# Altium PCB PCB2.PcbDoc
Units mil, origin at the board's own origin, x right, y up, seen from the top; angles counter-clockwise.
Board outline 6000 x 4000 mil, 2 copper layers (Top Layer, Bottom Layer); 84 components, 0 nets, 252 pads, 0 vias.
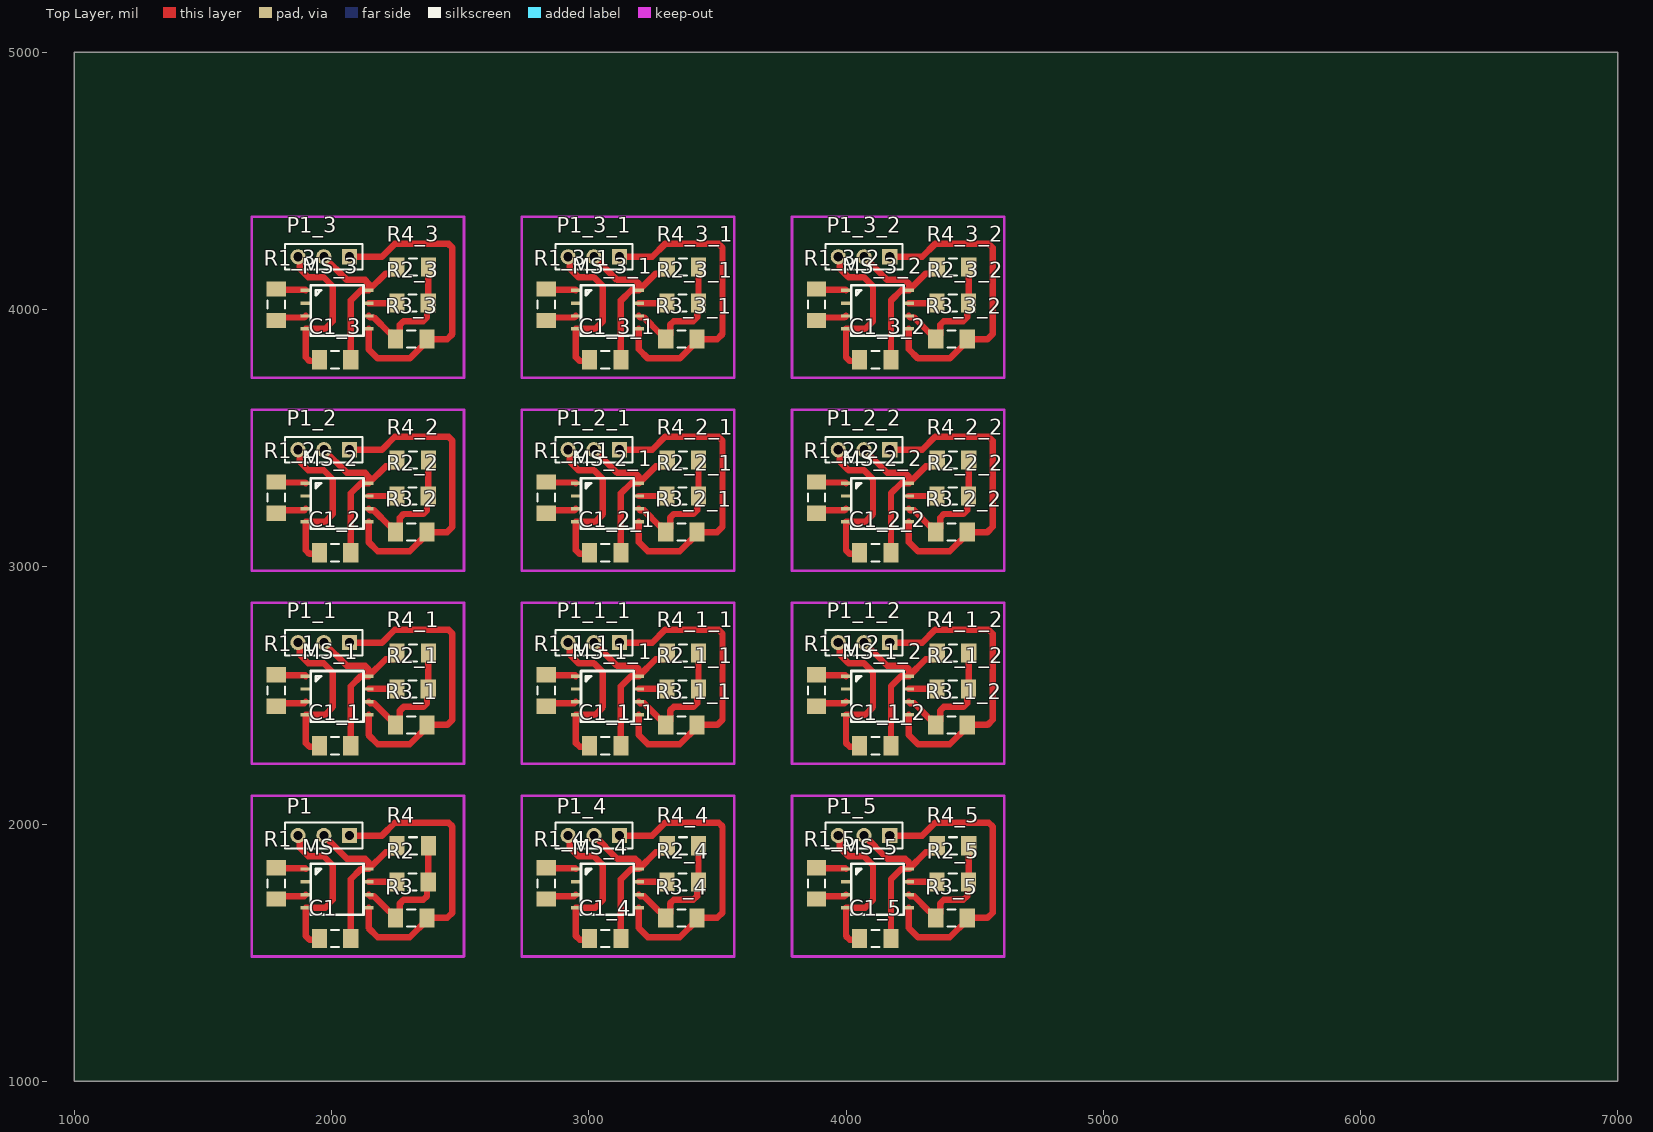
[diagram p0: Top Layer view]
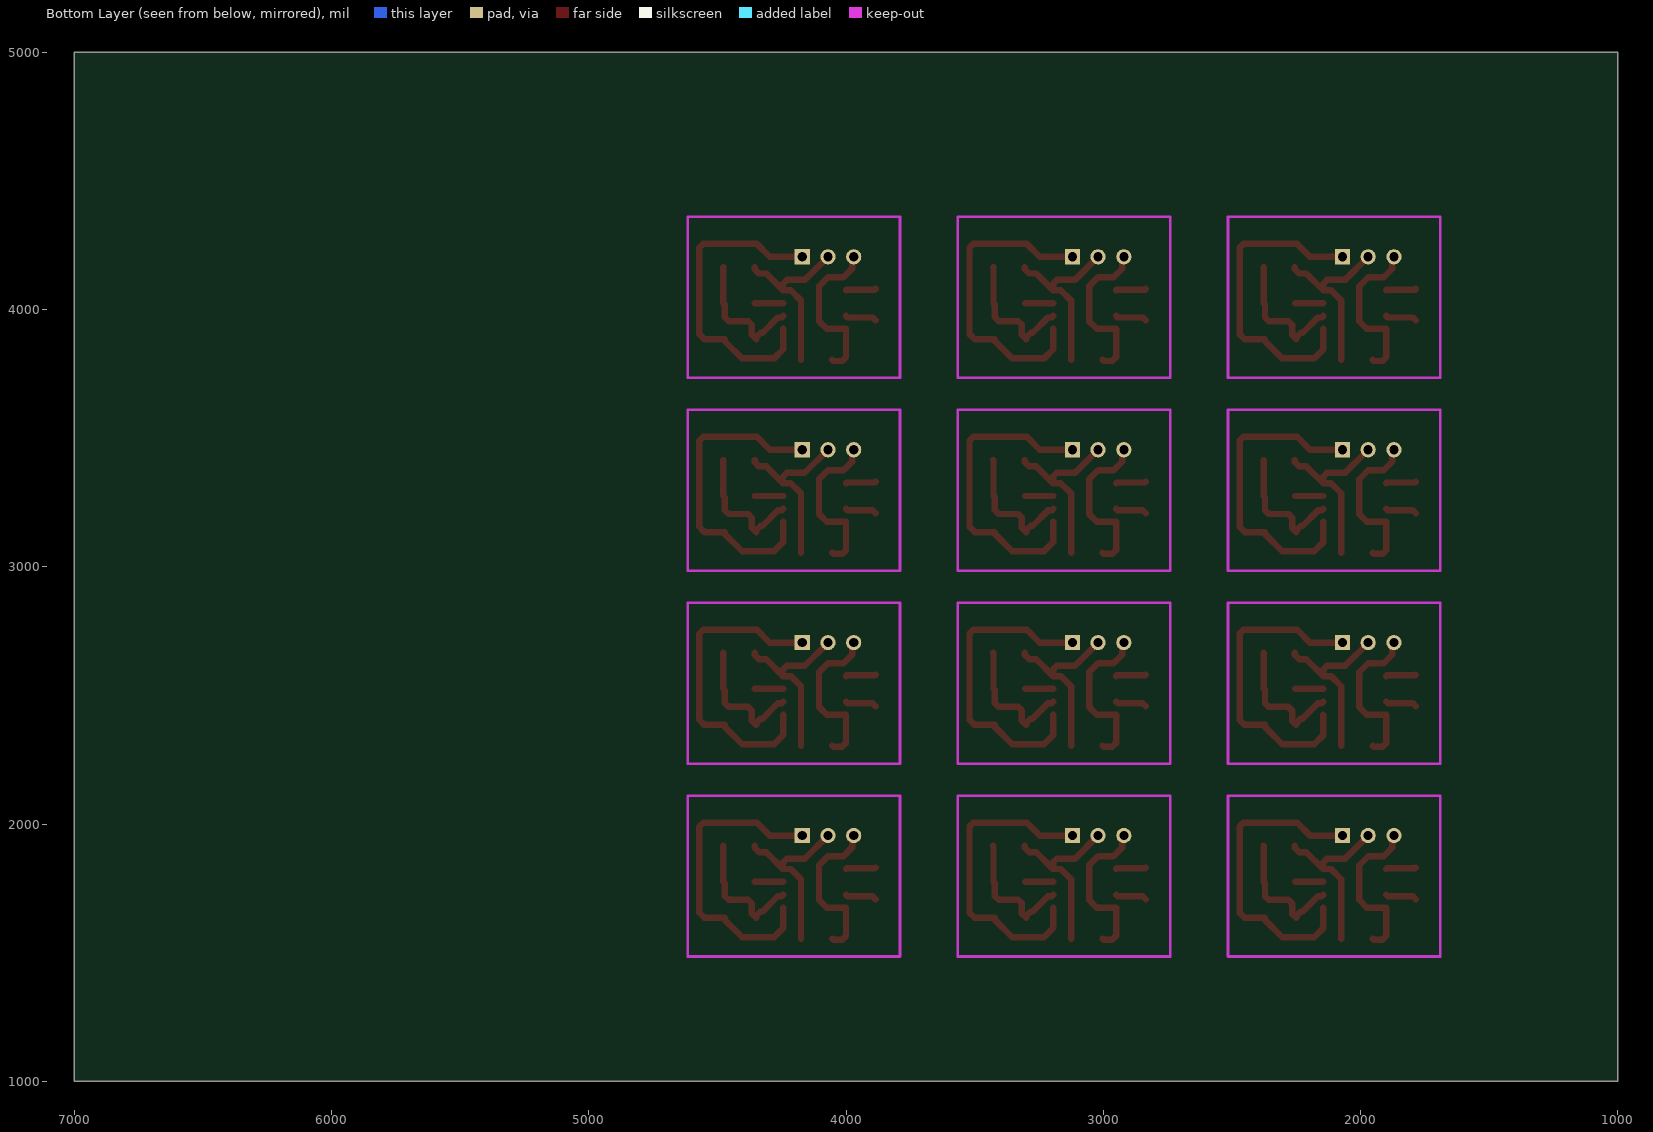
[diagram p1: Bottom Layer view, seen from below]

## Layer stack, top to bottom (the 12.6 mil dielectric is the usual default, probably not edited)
Top Solder: solder mask 0.4, Solder Resist, Dk 3.5
Top Layer: signal copper 1.4
Dielectric 1: dielectric 12.6, FR-4, Dk 4.8
Bottom Layer: signal copper 1.4
Bottom Solder: solder mask 0.4, Solder Resist, Dk 3.5

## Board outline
1000,1000 7000,1000 7000,5000 1000,5000

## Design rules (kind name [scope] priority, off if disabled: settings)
Clearance [All] p1: gap=10 ignorepadtopadclearanceinfootprint=FALSE except(0: Arc-Hole Track-Hole SMDPad-Hole THPad-Hole Via-Hole Fill-Hole Poly-Hole Region-Hole Text-Hole)
PolygonConnect [All] p1: connectstyle=Relief reliefconductorwidth=10 reliefentries=4 polygonreliefangle="90 Angle" airgapwidth=10
RoutingVias [All] p1: holewidth=28 width=50 viastyle="Through Hole" minholewidth=28 minwidth=50 maxholewidth=28 maxwidth=50
SolderMaskExpansion [All] p1: expansion=4
Width [All] p1: maxlimit=10 minlimit=10 preferedwidth=10
30 further rules are at their usual default settings.

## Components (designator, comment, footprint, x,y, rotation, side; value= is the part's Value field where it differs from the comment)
C1 "Cap" CAPC3216M 2013.98,1554.53 r0 top value=0.1muF
C1_1 "Cap" CAPC3216M 2013.98,2304.53 r0 top value=0.1muF (schematic designator C1)
C1_1_1 "Cap" CAPC3216M 3063.98,2304.53 r0 top value=0.1muF (schematic designator C1)
C1_1_2 "Cap" CAPC3216M 4113.98,2304.53 r0 top value=0.1muF (schematic designator C1)
C1_2 "Cap" CAPC3216M 2013.98,3054.53 r0 top value=0.1muF (schematic designator C1)
C1_2_1 "Cap" CAPC3216M 3063.98,3054.53 r0 top value=0.1muF (schematic designator C1)
C1_2_2 "Cap" CAPC3216M 4113.98,3054.53 r0 top value=0.1muF (schematic designator C1)
C1_3 "Cap" CAPC3216M 2013.98,3804.53 r0 top value=0.1muF (schematic designator C1)
C1_3_1 "Cap" CAPC3216M 3063.98,3804.53 r0 top value=0.1muF (schematic designator C1)
C1_3_2 "Cap" CAPC3216M 4113.98,3804.53 r0 top value=0.1muF (schematic designator C1)
C1_4 "Cap" CAPC3216M 3063.98,1554.53 r0 top value=0.1muF (schematic designator C1)
C1_5 "Cap" CAPC3216M 4113.98,1554.53 r0 top value=0.1muF (schematic designator C1)
MS "MagnetSensor" AD22151 1900,1825 r0 top
MS_1 "MagnetSensor" AD22151 1900,2575 r0 top (schematic designator MS)
MS_1_1 "MagnetSensor" AD22151 2950,2575 r0 top (schematic designator MS)
MS_1_2 "MagnetSensor" AD22151 4000,2575 r0 top (schematic designator MS)
MS_2 "MagnetSensor" AD22151 1900,3325 r0 top (schematic designator MS)
MS_2_1 "MagnetSensor" AD22151 2950,3325 r0 top (schematic designator MS)
MS_2_2 "MagnetSensor" AD22151 4000,3325 r0 top (schematic designator MS)
MS_3 "MagnetSensor" AD22151 1900,4075 r0 top (schematic designator MS)
MS_3_1 "MagnetSensor" AD22151 2950,4075 r0 top (schematic designator MS)
MS_3_2 "MagnetSensor" AD22151 4000,4075 r0 top (schematic designator MS)
MS_4 "MagnetSensor" AD22151 2950,1825 r0 top (schematic designator MS)
MS_5 "MagnetSensor" AD22151 4000,1825 r0 top (schematic designator MS)
P1 "Header 3" HDR1X3 2070,1955 r180 top (schematic designator P?)
P1_1 "Header 3" HDR1X3 2070,2705 r180 top (schematic designator P?)
P1_1_1 "Header 3" HDR1X3 3120,2705 r180 top (schematic designator P?)
P1_1_2 "Header 3" HDR1X3 4170,2705 r180 top (schematic designator P?)
P1_2 "Header 3" HDR1X3 2070,3455 r180 top (schematic designator P?)
P1_2_1 "Header 3" HDR1X3 3120,3455 r180 top (schematic designator P?)
P1_2_2 "Header 3" HDR1X3 4170,3455 r180 top (schematic designator P?)
P1_3 "Header 3" HDR1X3 2070,4205 r180 top (schematic designator P?)
P1_3_1 "Header 3" HDR1X3 3120,4205 r180 top (schematic designator P?)
P1_3_2 "Header 3" HDR1X3 4170,4205 r180 top (schematic designator P?)
P1_4 "Header 3" HDR1X3 3120,1955 r180 top (schematic designator P?)
P1_5 "Header 3" HDR1X3 4170,1955 r180 top (schematic designator P?)
R1 "Res3" RESC3216M 1785,1768.98 r90 top value=4.7K
R1_1 "Res3" RESC3216M 1785,2518.98 r90 top value=4.7K (schematic designator R1)
R1_1_1 "Res3" RESC3216M 2835,2518.98 r90 top value=4.7K (schematic designator R1)
R1_1_2 "Res3" RESC3216M 3885,2518.98 r90 top value=4.7K (schematic designator R1)
R1_2 "Res3" RESC3216M 1785,3268.98 r90 top value=4.7K (schematic designator R1)
R1_2_1 "Res3" RESC3216M 2835,3268.98 r90 top value=4.7K (schematic designator R1)
R1_2_2 "Res3" RESC3216M 3885,3268.98 r90 top value=4.7K (schematic designator R1)
R1_3 "Res3" RESC3216M 1785,4018.98 r90 top value=4.7K (schematic designator R1)
R1_3_1 "Res3" RESC3216M 2835,4018.98 r90 top value=4.7K (schematic designator R1)
R1_3_2 "Res3" RESC3216M 3885,4018.98 r90 top value=4.7K (schematic designator R1)
R1_4 "Res3" RESC3216M 2835,1768.98 r90 top value=4.7K (schematic designator R1)
R1_5 "Res3" RESC3216M 3885,1768.98 r90 top value=4.7K (schematic designator R1)
R2 "Res3" RESC3216M 2315,1775 r0 top value=4.7K
R2_1 "Res3" RESC3216M 2315,2525 r0 top value=4.7K (schematic designator R2)
R2_1_1 "Res3" RESC3216M 3365,2525 r0 top value=4.7K (schematic designator R2)
R2_1_2 "Res3" RESC3216M 4415,2525 r0 top value=4.7K (schematic designator R2)
R2_2 "Res3" RESC3216M 2315,3275 r0 top value=4.7K (schematic designator R2)
R2_2_1 "Res3" RESC3216M 3365,3275 r0 top value=4.7K (schematic designator R2)
R2_2_2 "Res3" RESC3216M 4415,3275 r0 top value=4.7K (schematic designator R2)
R2_3 "Res3" RESC3216M 2315,4025 r0 top value=4.7K (schematic designator R2)
R2_3_1 "Res3" RESC3216M 3365,4025 r0 top value=4.7K (schematic designator R2)
R2_3_2 "Res3" RESC3216M 4415,4025 r0 top value=4.7K (schematic designator R2)
R2_4 "Res3" RESC3216M 3365,1775 r0 top value=4.7K (schematic designator R2)
R2_5 "Res3" RESC3216M 4415,1775 r0 top value=4.7K (schematic designator R2)
R3 "Res3" RESC3216M 2310,1635 r0 top value=4.7K
R3_1 "Res3" RESC3216M 2310,2385 r0 top value=4.7K (schematic designator R3)
R3_1_1 "Res3" RESC3216M 3360,2385 r0 top value=4.7K (schematic designator R3)
R3_1_2 "Res3" RESC3216M 4410,2385 r0 top value=4.7K (schematic designator R3)
R3_2 "Res3" RESC3216M 2310,3135 r0 top value=4.7K (schematic designator R3)
R3_2_1 "Res3" RESC3216M 3360,3135 r0 top value=4.7K (schematic designator R3)
R3_2_2 "Res3" RESC3216M 4410,3135 r0 top value=4.7K (schematic designator R3)
R3_3 "Res3" RESC3216M 2310,3885 r0 top value=4.7K (schematic designator R3)
R3_3_1 "Res3" RESC3216M 3360,3885 r0 top value=4.7K (schematic designator R3)
R3_3_2 "Res3" RESC3216M 4410,3885 r0 top value=4.7K (schematic designator R3)
R3_4 "Res3" RESC3216M 3360,1635 r0 top value=4.7K (schematic designator R3)
R3_5 "Res3" RESC3216M 4410,1635 r0 top value=4.7K (schematic designator R3)
R4 "Res3" RESC3216M 2316.02,1915 r0 top value=4.7K
R4_1 "Res3" RESC3216M 2316.02,2665 r0 top value=4.7K (schematic designator R4)
R4_1_1 "Res3" RESC3216M 3366.02,2665 r0 top value=4.7K (schematic designator R4)
R4_1_2 "Res3" RESC3216M 4416.02,2665 r0 top value=4.7K (schematic designator R4)
R4_2 "Res3" RESC3216M 2316.02,3415 r0 top value=4.7K (schematic designator R4)
R4_2_1 "Res3" RESC3216M 3366.02,3415 r0 top value=4.7K (schematic designator R4)
R4_2_2 "Res3" RESC3216M 4416.02,3415 r0 top value=4.7K (schematic designator R4)
R4_3 "Res3" RESC3216M 2316.02,4165 r0 top value=4.7K (schematic designator R4)
R4_3_1 "Res3" RESC3216M 3366.02,4165 r0 top value=4.7K (schematic designator R4)
R4_3_2 "Res3" RESC3216M 4416.02,4165 r0 top value=4.7K (schematic designator R4)
R4_4 "Res3" RESC3216M 3366.02,1915 r0 top value=4.7K (schematic designator R4)
R4_5 "Res3" RESC3216M 4416.02,1915 r0 top value=4.7K (schematic designator R4)

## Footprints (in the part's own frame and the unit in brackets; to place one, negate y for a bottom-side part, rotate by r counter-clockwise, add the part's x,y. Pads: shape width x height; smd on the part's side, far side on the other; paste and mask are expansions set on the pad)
AD22151 [mm] "Magnetic Sensor"
  rect 1x0.33 smd: 1(0,0) 2(0,-1.27) 3(0,-2.54) 4(0,-3.81) 5(6.2,-3.81) 6(6.2,-2.54) 7(6.2,-1.27) 8(6.2,0)
  silkscreen extent 0.5,-4.5 5.7,0.5
CAPC3216M [mm] "Chip Capacitor, Body 3.2x1.6mm, IPC Low Density"
  rect 1.5x1.9 smd: 1(-1.55,0) 2(1.55,0)
  silkscreen extent -0.4,-0.85 0.4,0.85, body extent -1.7,-0.9 1.7,0.9, height 1.35
HDR1X3 [mm] "Connector; Header; 3 Position"
  rect 1.5x1.5 hole 0.9: 1(0,0)
  round 1.5 hole 0.9: 2(2.54,0) 3(5.08,0)
  silkscreen extent -1.27,-1.27 6.35,1.27
RESC3216M [mm] "Chip Resistor, Body 3.2x1.6mm, IPC Low Density"
  rect 1.5x1.9 smd: 1(-1.55,0) 2(1.55,0)
  silkscreen extent -0.4,-0.85 0.4,0.85, body extent -1.68,-0.87 1.68,0.87, height 0.71

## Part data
C1 C1_1 C1_1_1 C1_1_2 C1_2 C1_2_1 C1_2_2 C1_3 C1_3_1 C1_3_2 C1_4 C1_5: "Capacitor"
MS MS_1 MS_1_1 MS_1_2 MS_2 MS_2_1 MS_2_2 MS_3 MS_3_1 MS_3_2 MS_4 MS_5: library part Component_1
P1 P1_1 P1_1_1 P1_1_2 P1_2 P1_2_1 P1_2_2 P1_3 P1_3_1 P1_3_2 P1_4 P1_5: "Header, 3-Pin"
R1 R1_1 R1_1_1 R1_1_2 R1_2 R1_2_1 R1_2_2 R1_3 R1_3_1 R1_3_2 R1_4 R1_5 R2 R2_1 R2_1_1 R2_1_2 R2_2 R2_2_1 R2_2_2 R2_3 R2_3_1 R2_3_2 R2_4 R2_5 R3 R3_1 R3_1_1 R3_1_2 R3_2 R3_2_1 R3_2_2 R3_3 R3_3_1 R3_3_2 R3_4 R3_5 R4 R4_1 R4_1_1 R4_1_2 R4_2 R4_2_1 R4_2_2 R4_3 R4_3_1 R4_3_2 R4_4 R4_5: "Resistor"

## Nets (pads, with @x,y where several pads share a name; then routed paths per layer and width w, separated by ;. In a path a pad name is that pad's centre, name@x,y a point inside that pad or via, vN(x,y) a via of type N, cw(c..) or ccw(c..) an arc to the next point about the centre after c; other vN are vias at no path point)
pads on no net: C1.1 C1.2 C1_1.1 C1_1.2 C1_1_1.1 C1_1_1.2 C1_1_2.1 C1_1_2.2 C1_2.1 C1_2.2 C1_2_1.1 C1_2_1.2 C1_2_2.1 C1_2_2.2 C1_3.1 C1_3.2 C1_3_1.1 C1_3_1.2 C1_3_2.1 C1_3_2.2 C1_4.1 C1_4.2 C1_5.1 C1_5.2 MS.1 MS.2 MS.3 MS.4 MS.5 MS.6 MS.7 MS.8 MS_1.1 MS_1.2 MS_1.3 MS_1.4 MS_1.5 MS_1.6 MS_1.7 MS_1.8 MS_1_1.1 MS_1_1.2 MS_1_1.3 MS_1_1.4 MS_1_1.5 MS_1_1.6 MS_1_1.7 MS_1_1.8 MS_1_2.1 MS_1_2.2 MS_1_2.3 MS_1_2.4 MS_1_2.5 MS_1_2.6 MS_1_2.7 MS_1_2.8 MS_2.1 MS_2.2 MS_2.3 MS_2.4 MS_2.5 MS_2.6 MS_2.7 MS_2.8 MS_2_1.1 MS_2_1.2 MS_2_1.3 MS_2_1.4 MS_2_1.5 MS_2_1.6 MS_2_1.7 MS_2_1.8 MS_2_2.1 MS_2_2.2 MS_2_2.3 MS_2_2.4 MS_2_2.5 MS_2_2.6 MS_2_2.7 MS_2_2.8 MS_3.1 MS_3.2 MS_3.3 MS_3.4 MS_3.5 MS_3.6 MS_3.7 MS_3.8 MS_3_1.1 MS_3_1.2 MS_3_1.3 MS_3_1.4 MS_3_1.5 MS_3_1.6 MS_3_1.7 MS_3_1.8 MS_3_2.1 MS_3_2.2 MS_3_2.3 MS_3_2.4 MS_3_2.5 MS_3_2.6 MS_3_2.7 MS_3_2.8 MS_4.1 MS_4.2 MS_4.3 MS_4.4 MS_4.5 MS_4.6 MS_4.7 MS_4.8 MS_5.1 MS_5.2 MS_5.3 MS_5.4 MS_5.5 MS_5.6 MS_5.7 MS_5.8 P1.1 P1.2 P1.3 P1_1.1 P1_1.2 P1_1.3 P1_1_1.1 P1_1_1.2 P1_1_1.3 P1_1_2.1 P1_1_2.2 P1_1_2.3 P1_2.1 P1_2.2 P1_2.3 P1_2_1.1 P1_2_1.2 P1_2_1.3 P1_2_2.1 P1_2_2.2 P1_2_2.3 P1_3.1 P1_3.2 P1_3.3 P1_3_1.1 P1_3_1.2 P1_3_1.3 P1_3_2.1 P1_3_2.2 P1_3_2.3 P1_4.1 P1_4.2 P1_4.3 P1_5.1 P1_5.2 P1_5.3 R1.1 R1.2 R1_1.1 R1_1.2 R1_1_1.1 R1_1_1.2 R1_1_2.1 R1_1_2.2 R1_2.1 R1_2.2 R1_2_1.1 R1_2_1.2 R1_2_2.1 R1_2_2.2 R1_3.1 R1_3.2 R1_3_1.1 R1_3_1.2 R1_3_2.1 R1_3_2.2 R1_4.1 R1_4.2 R1_5.1 R1_5.2 R2.1 R2.2 R2_1.1 R2_1.2 R2_1_1.1 R2_1_1.2 R2_1_2.1 R2_1_2.2 R2_2.1 R2_2.2 R2_2_1.1 R2_2_1.2 R2_2_2.1 R2_2_2.2 R2_3.1 R2_3.2 R2_3_1.1 R2_3_1.2 R2_3_2.1 R2_3_2.2 R2_4.1 R2_4.2 R2_5.1 R2_5.2 R3.1 R3.2 R3_1.1 R3_1.2 R3_1_1.1 R3_1_1.2 R3_1_2.1 R3_1_2.2 R3_2.1 R3_2.2 R3_2_1.1 R3_2_1.2 R3_2_2.1 R3_2_2.2 R3_3.1 R3_3.2 R3_3_1.1 R3_3_1.2 R3_3_2.1 R3_3_2.2 R3_4.1 R3_4.2 R3_5.1 R3_5.2 R4.1 R4.2 R4_1.1 R4_1.2 R4_1_1.1 R4_1_1.2 R4_1_2.1 R4_1_2.2 R4_2.1 R4_2.2 R4_2_1.1 R4_2_1.2 R4_2_2.1 R4_2_2.2 R4_3.1 R4_3.2 R4_3_1.1 R4_3_1.2 R4_3_2.1 R4_3_2.2 R4_4.1 R4_4.2 R4_5.1 R4_5.2
copper on no net: | length 41322.9
  Top Layer w10: 2075,1554.53 2075.91,1555.43 ; 2075,2304.53 2075.91,2305.43 ; 2075,3054.53 2075.91,3055.43 ; 2075,3804.53 2075.91,3805.43 ; 3125,1554.53 3125.91,1555.43 ; 3125,2304.53 3125.91,2305.43 ; 3125,3054.53 3125.91,3055.43 ; 3125,3804.53 3125.91,3805.43 ; 4175,1554.53 4175.91,1555.43 ; 4175,2304.53 4175.91,2305.43 ; 4175,3054.53 4175.91,3055.43 ; 4175,3804.53 4175.91,3805.43
  Top Layer w25: 1785,1707.95 1796.04,1719 1894,1719 1900,1725 ; 1785,1830 1787.5,1827.5 1897.5,1827.5 1900,1825 ; 1785,2457.95 1796.04,2469 1894,2469 1900,2475 ; 1785,2580 1787.5,2577.5 1897.5,2577.5 1900,2575 ; 1785,3207.95 1796.04,3219 1894,3219 1900,3225 ; 1785,3330 1787.5,3327.5 1897.5,3327.5 1900,3325 ; 1785,3957.95 1796.04,3969 1894,3969 1900,3975 ; 1785,4080 1787.5,4077.5 1897.5,4077.5 1900,4075 ; 1870,1955 1876.52,1948.48 1876.52,1908.48 1910,1875 1970,1875 2005,1840 2005,1705 1975,1675 1900,1675 1900,1564.64 1914.64,1550 1948.43,1550 1952.95,1554.53 ; 1870,2705 1876.52,2698.48 1876.52,2658.48 1910,2625 1970,2625 2005,2590 2005,2455 1975,2425 1900,2425 1900,2314.64 1914.64,2300 1948.43,2300 1952.95,2304.53 ; 1870,3455 1876.52,3448.48 1876.52,3408.48 1910,3375 1970,3375 2005,3340 2005,3205 1975,3175 1900,3175 1900,3064.64 1914.64,3050 1948.43,3050 1952.95,3054.53 ; 1870,4205 1876.52,4198.48 1876.52,4158.48 1910,4125 1970,4125 2005,4090 2005,3955 1975,3925 1900,3925 1900,3814.64 1914.64,3800 1948.43,3800 1952.95,3804.53 ; 1970,1955 2060,1865 2130.36,1865 2145,1850.36 2145,1825.91 2144.09,1825 ; 1970,2705 2060,2615 2130.36,2615 2145,2600.36 2145,2575.91 2144.09,2575 ; 1970,3455 2060,3365 2130.36,3365 2145,3350.36 2145,3325.91 2144.09,3325 ; 1970,4205 2060,4115 2130.36,4115 2145,4100.36 2145,4075.91 2144.09,4075 ; 2070,1955 2196.25,1955 2246.25,2005 2455,2005 2470,1990 2470,1655 2450,1635 2371.02,1635 2371.02,1627.13 2303.9,1560 2180,1560 2144.09,1595.91 2144.09,1675 ; 2070,2705 2196.25,2705 2246.25,2755 2455,2755 2470,2740 2470,2405 2450,2385 2371.02,2385 2371.02,2377.13 2303.9,2310 2180,2310 2144.09,2345.91 2144.09,2425 ; 2070,3455 2196.25,3455 2246.25,3505 2455,3505 2470,3490 2470,3155 2450,3135 2371.02,3135 2371.02,3127.13 2303.9,3060 2180,3060 2144.09,3095.91 2144.09,3175 ; 2070,4205 2196.25,4205 2246.25,4255 2455,4255 2470,4240 2470,3905 2450,3885 2371.02,3885 2371.02,3877.13 2303.9,3810 2180,3810 2144.09,3845.91 2144.09,3925 ; 2075,1554.53 2075,1785.36 2114.64,1825 2144.09,1825 ; 2075,2304.53 2075,2535.36 2114.64,2575 2144.09,2575 ; 2075,3054.53 2075,3285.36 2114.64,3325 2144.09,3325 ; 2075,3804.53 2075,4035.36 2114.64,4075 2144.09,4075 ; 2144.09,1725 2150.1,1719 2164.98,1719 2224.07,1659.9 2231.95,1659.9 2248.98,1642.87 2248.98,1635 2266,1652.03 2266,1691 2280,1705 2356.38,1705 2371.02,1719.64 2371.02,1770 2376.02,1775 2376.54,1775.51 2376.54,1914.49 2377.05,1915 ; 2144.09,1775 2253.98,1775 ; 2144.09,2475 2150.1,2469 2164.98,2469 2224.07,2409.9 2231.95,2409.9 2248.98,2392.87 2248.98,2385 2266,2402.03 2266,2441 2280,2455 2356.38,2455 2371.02,2469.64 2371.02,2520 2376.02,2525 2376.54,2525.51 2376.54,2664.49 2377.05,2665 ; 2144.09,2525 2253.98,2525 ; 2144.09,3225 2150.1,3219 2164.98,3219 2224.07,3159.9 2231.95,3159.9 2248.98,3142.87 2248.98,3135 2266,3152.03 2266,3191 2280,3205 2356.38,3205 2371.02,3219.64 2371.02,3270 2376.02,3275 2376.54,3275.51 2376.54,3414.49 2377.05,3415 ; 2144.09,3275 2253.98,3275 ; 2144.09,3975 2150.1,3969 2164.98,3969 2224.07,3909.9 2231.95,3909.9 2248.98,3892.87 2248.98,3885 2266,3902.03 2266,3941 2280,3955 2356.38,3955 2371.02,3969.64 2371.02,4020 2376.02,4025 2376.54,4025.51 2376.54,4164.49 2377.05,4165 ; 2144.09,4025 2253.98,4025 ; 2255,1915 2255,1907.13 2237.97,1890.1 2210.37,1890.1 2145.28,1825 2144.09,1825 ; 2255,2665 2255,2657.13 2237.97,2640.1 2210.37,2640.1 2145.28,2575 2144.09,2575 ; 2255,3415 2255,3407.13 2237.97,3390.1 2210.37,3390.1 2145.28,3325 2144.09,3325 ; 2255,4165 2255,4157.13 2237.97,4140.1 2210.37,4140.1 2145.28,4075 2144.09,4075 ; 2835,1707.95 2846.04,1719 2944,1719 2950,1725 ; 2835,1830 2837.5,1827.5 2947.5,1827.5 2950,1825 ; 2835,2457.95 2846.04,2469 2944,2469 2950,2475 ; 2835,2580 2837.5,2577.5 2947.5,2577.5 2950,2575 ; 2835,3207.95 2846.04,3219 2944,3219 2950,3225 ; 2835,3330 2837.5,3327.5 2947.5,3327.5 2950,3325 ; 2835,3957.95 2846.04,3969 2944,3969 2950,3975 ; 2835,4080 2837.5,4077.5 2947.5,4077.5 2950,4075 ; 2920,1955 2926.52,1948.48 2926.52,1908.48 2960,1875 3020,1875 3055,1840 3055,1705 3025,1675 2950,1675 2950,1564.64 2964.64,1550 2998.43,1550 3002.95,1554.53 ; 2920,2705 2926.52,2698.48 2926.52,2658.48 2960,2625 3020,2625 3055,2590 3055,2455 3025,2425 2950,2425 2950,2314.64 2964.64,2300 2998.43,2300 3002.95,2304.53 ; 2920,3455 2926.52,3448.48 2926.52,3408.48 2960,3375 3020,3375 3055,3340 3055,3205 3025,3175 2950,3175 2950,3064.64 2964.64,3050 2998.43,3050 3002.95,3054.53 ; 2920,4205 2926.52,4198.48 2926.52,4158.48 2960,4125 3020,4125 3055,4090 3055,3955 3025,3925 2950,3925 2950,3814.64 2964.64,3800 2998.43,3800 3002.95,3804.53 ; 3020,1955 3110,1865 3180.36,1865 3195,1850.36 3195,1825.91 3194.09,1825 ; 3020,2705 3110,2615 3180.36,2615 3195,2600.36 3195,2575.91 3194.09,2575 ; 3020,3455 3110,3365 3180.36,3365 3195,3350.36 3195,3325.91 3194.09,3325 ; 3020,4205 3110,4115 3180.36,4115 3195,4100.36 3195,4075.91 3194.09,4075 ; 3120,1955 3246.25,1955 3296.25,2005 3505,2005 3520,1990 3520,1655 3500,1635 3421.02,1635 3421.02,1627.13 3353.9,1560 3230,1560 3194.09,1595.91 3194.09,1675 ; 3120,2705 3246.25,2705 3296.25,2755 3505,2755 3520,2740 3520,2405 3500,2385 3421.02,2385 3421.02,2377.13 3353.9,2310 3230,2310 3194.09,2345.91 3194.09,2425 ; 3120,3455 3246.25,3455 3296.25,3505 3505,3505 3520,3490 3520,3155 3500,3135 3421.02,3135 3421.02,3127.13 3353.9,3060 3230,3060 3194.09,3095.91 3194.09,3175 ; 3120,4205 3246.25,4205 3296.25,4255 3505,4255 3520,4240 3520,3905 3500,3885 3421.02,3885 3421.02,3877.13 3353.9,3810 3230,3810 3194.09,3845.91 3194.09,3925 ; 3125,1554.53 3125,1785.36 3164.64,1825 3194.09,1825 ; 3125,2304.53 3125,2535.36 3164.64,2575 3194.09,2575 ; 3125,3054.53 3125,3285.36 3164.64,3325 3194.09,3325 ; 3125,3804.53 3125,4035.36 3164.64,4075 3194.09,4075 ; 3194.09,1725 3200.1,1719 3214.98,1719 3274.07,1659.9 3281.95,1659.9 3298.98,1642.87 3298.98,1635 3316,1652.03 3316,1691 3330,1705 3406.38,1705 3421.02,1719.64 3421.02,1770 3426.02,1775 3426.54,1775.51 3426.54,1914.49 3427.05,1915 ; 3194.09,1775 3303.98,1775 ; 3194.09,2475 3200.1,2469 3214.98,2469 3274.07,2409.9 3281.95,2409.9 3298.98,2392.87 3298.98,2385 3316,2402.03 3316,2441 3330,2455 3406.38,2455 3421.02,2469.64 3421.02,2520 3426.02,2525 3426.54,2525.51 3426.54,2664.49 3427.05,2665 ; 3194.09,2525 3303.98,2525 ; 3194.09,3225 3200.1,3219 3214.98,3219 3274.07,3159.9 3281.95,3159.9 3298.98,3142.87 3298.98,3135 3316,3152.03 3316,3191 3330,3205 3406.38,3205 3421.02,3219.64 3421.02,3270 3426.02,3275 3426.54,3275.51 3426.54,3414.49 3427.05,3415 ; 3194.09,3275 3303.98,3275 ; 3194.09,3975 3200.1,3969 3214.98,3969 3274.07,3909.9 3281.95,3909.9 3298.98,3892.87 3298.98,3885 3316,3902.03 3316,3941 3330,3955 3406.38,3955 3421.02,3969.64 3421.02,4020 3426.02,4025 3426.54,4025.51 3426.54,4164.49 3427.05,4165 ; 3194.09,4025 3303.98,4025 ; 3305,1915 3305,1907.13 3287.97,1890.1 3260.37,1890.1 3195.28,1825 3194.09,1825 ; 3305,2665 3305,2657.13 3287.97,2640.1 3260.37,2640.1 3195.28,2575 3194.09,2575 ; 3305,3415 3305,3407.13 3287.97,3390.1 3260.37,3390.1 3195.28,3325 3194.09,3325 ; 3305,4165 3305,4157.13 3287.97,4140.1 3260.37,4140.1 3195.28,4075 3194.09,4075 ; 3885,1707.95 3896.04,1719 3994,1719 4000,1725 ; 3885,1830 3887.5,1827.5 3997.5,1827.5 4000,1825 ; 3885,2457.95 3896.04,2469 3994,2469 4000,2475 ; 3885,2580 3887.5,2577.5 3997.5,2577.5 4000,2575 ; 3885,3207.95 3896.04,3219 3994,3219 4000,3225 ; 3885,3330 3887.5,3327.5 3997.5,3327.5 4000,3325 ; 3885,3957.95 3896.04,3969 3994,3969 4000,3975 ; 3885,4080 3887.5,4077.5 3997.5,4077.5 4000,4075 ; 3970,1955 3976.52,1948.48 3976.52,1908.48 4010,1875 4070,1875 4105,1840 4105,1705 4075,1675 4000,1675 4000,1564.64 4014.64,1550 4048.43,1550 4052.95,1554.53 ; 3970,2705 3976.52,2698.48 3976.52,2658.48 4010,2625 4070,2625 4105,2590 4105,2455 4075,2425 4000,2425 4000,2314.64 4014.64,2300 4048.43,2300 4052.95,2304.53 ; 3970,3455 3976.52,3448.48 3976.52,3408.48 4010,3375 4070,3375 4105,3340 4105,3205 4075,3175 4000,3175 4000,3064.64 4014.64,3050 4048.43,3050 4052.95,3054.53 ; 3970,4205 3976.52,4198.48 3976.52,4158.48 4010,4125 4070,4125 4105,4090 4105,3955 4075,3925 4000,3925 4000,3814.64 4014.64,3800 4048.43,3800 4052.95,3804.53 ; 4070,1955 4160,1865 4230.36,1865 4245,1850.36 4245,1825.91 4244.09,1825 ; 4070,2705 4160,2615 4230.36,2615 4245,2600.36 4245,2575.91 4244.09,2575 ; 4070,3455 4160,3365 4230.36,3365 4245,3350.36 4245,3325.91 4244.09,3325 ; 4070,4205 4160,4115 4230.36,4115 4245,4100.36 4245,4075.91 4244.09,4075 ; 4170,1955 4296.25,1955 4346.25,2005 4555,2005 4570,1990 4570,1655 4550,1635 4471.02,1635 4471.02,1627.13 4403.9,1560 4280,1560 4244.09,1595.91 4244.09,1675 ; 4170,2705 4296.25,2705 4346.25,2755 4555,2755 4570,2740 4570,2405 4550,2385 4471.02,2385 4471.02,2377.13 4403.9,2310 4280,2310 4244.09,2345.91 4244.09,2425 ; 4170,3455 4296.25,3455 4346.25,3505 4555,3505 4570,3490 4570,3155 4550,3135 4471.02,3135 4471.02,3127.13 4403.9,3060 4280,3060 4244.09,3095.91 4244.09,3175 ; 4170,4205 4296.25,4205 4346.25,4255 4555,4255 4570,4240 4570,3905 4550,3885 4471.02,3885 4471.02,3877.13 4403.9,3810 4280,3810 4244.09,3845.91 4244.09,3925 ; 4175,1554.53 4175,1785.36 4214.64,1825 4244.09,1825 ; 4175,2304.53 4175,2535.36 4214.64,2575 4244.09,2575 ; 4175,3054.53 4175,3285.36 4214.64,3325 4244.09,3325 ; 4175,3804.53 4175,4035.36 4214.64,4075 4244.09,4075 ; 4244.09,1725 4250.1,1719 4264.98,1719 4324.07,1659.9 4331.95,1659.9 4348.98,1642.87 4348.98,1635 4366,1652.03 4366,1691 4380,1705 4456.38,1705 4471.02,1719.64 4471.02,1770 4476.02,1775 4476.54,1775.51 4476.54,1914.49 4477.05,1915 ; 4244.09,1775 4353.98,1775 ; 4244.09,2475 4250.1,2469 4264.98,2469 4324.07,2409.9 4331.95,2409.9 4348.98,2392.87 4348.98,2385 4366,2402.03 4366,2441 4380,2455 4456.38,2455 4471.02,2469.64 4471.02,2520 4476.02,2525 4476.54,2525.51 4476.54,2664.49 4477.05,2665 ; 4244.09,2525 4353.98,2525 ; 4244.09,3225 4250.1,3219 4264.98,3219 4324.07,3159.9 4331.95,3159.9 4348.98,3142.87 4348.98,3135 4366,3152.03 4366,3191 4380,3205 4456.38,3205 4471.02,3219.64 4471.02,3270 4476.02,3275 4476.54,3275.51 4476.54,3414.49 4477.05,3415 ; 4244.09,3275 4353.98,3275 ; 4244.09,3975 4250.1,3969 4264.98,3969 4324.07,3909.9 4331.95,3909.9 4348.98,3892.87 4348.98,3885 4366,3902.03 4366,3941 4380,3955 4456.38,3955 4471.02,3969.64 4471.02,4020 4476.02,4025 4476.54,4025.51 4476.54,4164.49 4477.05,4165 ; 4244.09,4025 4353.98,4025 ; 4355,1915 4355,1907.13 4337.97,1890.1 4310.37,1890.1 4245.28,1825 4244.09,1825 ; 4355,2665 4355,2657.13 4337.97,2640.1 4310.37,2640.1 4245.28,2575 4244.09,2575 ; 4355,3415 4355,3407.13 4337.97,3390.1 4310.37,3390.1 4245.28,3325 4244.09,3325 ; 4355,4165 4355,4157.13 4337.97,4140.1 4310.37,4140.1 4245.28,4075 4244.09,4075

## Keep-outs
Keep-Out Layer:
  lines w10: 1695,2110 1690,2110 ; 1695,2860 1690,2860 ; 1695,3610 1690,3610 ; 1695,4360 1690,4360 ; 2745,2110 2740,2110 ; 2745,2860 2740,2860 ; 2745,3610 2740,3610 ; 2745,4360 2740,4360 ; 3795,2110 3790,2110 ; 3795,2860 3790,2860 ; 3795,3610 3790,3610 ; 3795,4360 3790,4360 ; 1690,2110 2515,2110 2515,1485 1690,1485 1690,2110 ; 1690,2860 2515,2860 2515,2235 1690,2235 1690,2860 ; 1690,3610 2515,3610 2515,2985 1690,2985 1690,3610 ; 1690,4360 2515,4360 2515,3735 1690,3735 1690,4360 ; 2740,2110 3565,2110 3565,1485 2740,1485 2740,2110 ; 2740,2860 3565,2860 3565,2235 2740,2235 2740,2860 ; 2740,3610 3565,3610 3565,2985 2740,2985 2740,3610 ; 2740,4360 3565,4360 3565,3735 2740,3735 2740,4360 ; 3790,2110 4615,2110 4615,1485 3790,1485 3790,2110 ; 3790,2860 4615,2860 4615,2235 3790,2235 3790,2860 ; 3790,3610 4615,3610 4615,2985 3790,2985 3790,3610 ; 3790,4360 4615,4360 4615,3735 3790,3735 3790,4360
